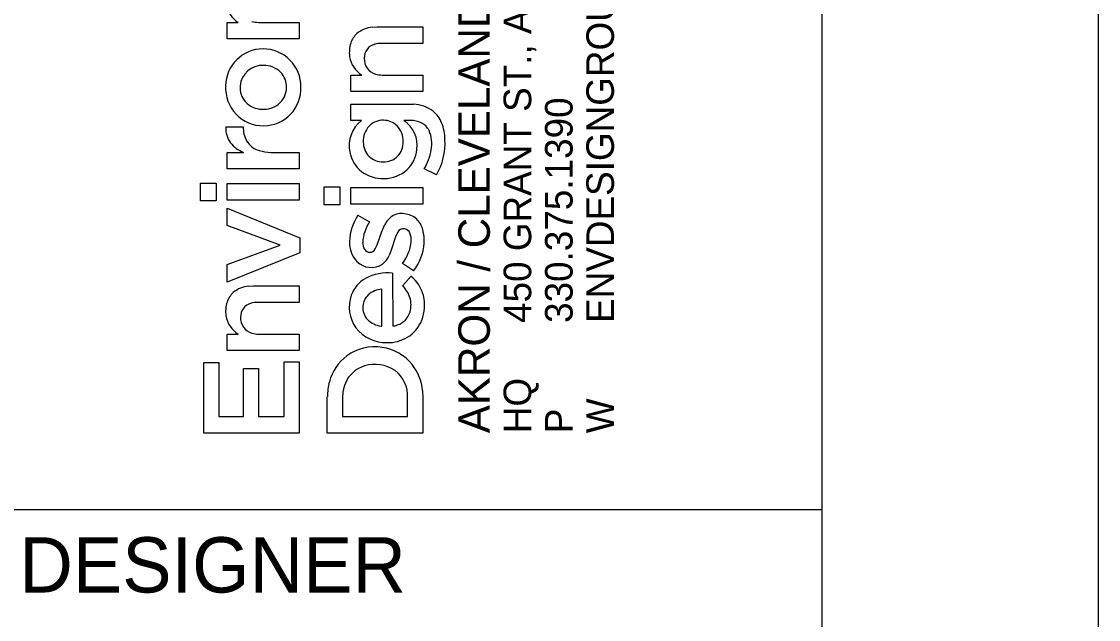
# Model space of a CAD drawing. Extents: x 0 to 34, y 0 to 22.
# Drawn here: x 32.054 to 34, y 2.301 to 3.382 of the extents above; entities that cross this region are included whole.
import ezdxf

# ---------------------------------------------------------------- set-up
doc = ezdxf.new("R2010")
doc.units = 0
for name, color, linetype in [('SH_Border', 7, 'Continuous'), ('SH_Cut_Line', 7, 'Continuous'), ('SH_Data', 7, 'Continuous'), ('SH_Text', 7, 'Continuous')]:
    doc.layers.add(name, color=color, linetype=linetype)

msp = doc.modelspace()

# ---------------------------------------------------------------- linework, layer by layer
at = {"layer": 'SH_Border'}
msp.add_line((32, 2.5), (33.5, 2.5), dxfattribs=at)
msp.add_lwpolyline([(1.5, 21.5), (33.5, 21.5), (33.5, 0.5), (1.5, 0.5)], close=True, dxfattribs=at)
at = {"layer": 'SH_Cut_Line'}
msp.add_lwpolyline([(0, 0), (34, 0), (34, 22), (0, 22)], close=True, dxfattribs=at)
at = {"layer": 'SH_Text'}
for p, q in [((32.4254, 3.3509), (32.4254, 3.3807)), ((32.4254, 3.3807), (32.4455, 3.3807)), ((32.4822, 3.3807), (32.5557, 3.3807)), ((32.5557, 3.3807), (32.5557, 3.351)), ((32.6878, 3.3722), (32.6963, 3.3727)), ((32.6963, 3.3727), (32.7792, 3.3727)), ((32.7792, 3.3727), (32.7792, 3.3429)), ((32.5557, 3.351), (32.4254, 3.3509)), ((32.7792, 3.3429), (32.7048, 3.3428)), ((32.6489, 3.2557), (32.6489, 3.2855)), ((32.6489, 3.2855), (32.669, 3.2855)), ((32.7057, 3.2855), (32.7791, 3.2855)), ((32.7791, 3.2855), (32.7792, 3.2558)), ((32.7792, 3.2558), (32.6489, 3.2557)), ((32.6489, 3.2034), (32.6489, 3.2332)), ((32.6489, 3.2332), (32.7524, 3.2332)), ((32.7524, 3.2332), (32.7619, 3.2329)), ((32.423, 3.1919), (32.4545, 3.1919)), ((32.6684, 3.2034), (32.6489, 3.2034)), ((32.7576, 3.2036), (32.7449, 3.2036)), ((32.4254, 3.1159), (32.4254, 3.1458)), ((32.4254, 3.1458), (32.4547, 3.1458)), ((32.5041, 3.1458), (32.5557, 3.1457)), ((32.5557, 3.1457), (32.5556, 3.1159)), ((32.5556, 3.1159), (32.4254, 3.1159)), ((32.8036, 3.1049), (32.7812, 3.116)), ((32.3771, 3.0582), (32.3771, 3.0903)), ((32.3771, 3.0903), (32.4054, 3.0903)), ((32.4054, 3.0903), (32.4054, 3.0582)), ((32.4254, 3.0594), (32.4254, 3.0893)), ((32.4254, 3.0893), (32.5557, 3.0893)), ((32.5557, 3.0893), (32.5557, 3.0594)), ((32.6005, 3.0511), (32.6005, 3.0832)), ((32.6005, 3.0832), (32.6289, 3.0832)), ((32.6289, 3.0832), (32.6289, 3.0511)), ((32.6489, 3.0523), (32.6489, 3.0822)), ((32.6489, 3.0822), (32.7792, 3.0822)), ((32.7792, 3.0822), (32.7792, 3.0523)), ((32.4054, 3.0582), (32.3771, 3.0582)), ((32.5557, 3.0594), (32.4254, 3.0594)), ((32.4254, 3.0133), (32.4254, 3.0446)), ((32.4254, 3.0446), (32.5567, 2.9913)), ((32.6289, 3.0511), (32.6005, 3.0511)), ((32.7792, 3.0523), (32.6489, 3.0523)), ((32.6615, 3.0321), (32.6827, 3.0203)), ((32.5212, 2.978), (32.4254, 3.0133)), ((32.6967, 2.9787), (32.7048, 3.0026)), ((32.7048, 3.0026), (32.7104, 3.0153)), ((32.7334, 3.001), (32.7298, 2.9933)), ((32.4254, 2.9429), (32.5212, 2.978)), ((32.5567, 2.9913), (32.5567, 2.9644)), ((32.693, 2.9712), (32.6967, 2.9787)), ((32.7298, 2.9933), (32.7221, 2.9688)), ((32.5567, 2.9644), (32.4254, 2.9109)), ((32.7221, 2.9688), (32.7182, 2.9592)), ((32.4254, 2.9109), (32.4254, 2.9429)), ((32.7621, 2.9314), (32.742, 2.9447)), ((32.7245, 2.9275), (32.7246, 2.8319)), ((32.7423, 2.9046), (32.7577, 2.922)), ((32.4644, 2.904), (32.4729, 2.9044)), ((32.4729, 2.9044), (32.5557, 2.9044)), ((32.5557, 2.9044), (32.5557, 2.8746)), ((32.7049, 2.8318), (32.7049, 2.8983)), ((32.5557, 2.8746), (32.4814, 2.8746)), ((32.7036, 2.8317), (32.7049, 2.8318)), ((32.4254, 2.7875), (32.4254, 2.8173)), ((32.4254, 2.8173), (32.4455, 2.8173)), ((32.4822, 2.8173), (32.5557, 2.8173)), ((32.5557, 2.8173), (32.5557, 2.7876)), ((32.5557, 2.7876), (32.4254, 2.7875)), ((32.383, 2.6379), (32.383, 2.766)), ((32.383, 2.766), (32.4101, 2.766)), ((32.4101, 2.766), (32.4101, 2.6683)), ((32.5286, 2.6683), (32.5286, 2.7672)), ((32.5286, 2.7672), (32.5557, 2.7672)), ((32.5557, 2.7672), (32.5557, 2.6379)), ((32.455, 2.6683), (32.455, 2.7549)), ((32.455, 2.7549), (32.4822, 2.7549)), ((32.4822, 2.7549), (32.4822, 2.6683)), ((32.6347, 2.7118), (32.6341, 2.7023)), ((32.7785, 2.715), (32.7792, 2.7021)), ((32.6064, 2.638), (32.6064, 2.704)), ((32.6341, 2.7023), (32.6341, 2.6684)), ((32.7515, 2.6683), (32.7515, 2.7024)), ((32.7792, 2.7021), (32.7792, 2.638)), ((32.4101, 2.6683), (32.455, 2.6683)), ((32.4822, 2.6683), (32.5286, 2.6683)), ((32.6341, 2.6684), (32.7515, 2.6683)), ((32.5557, 2.6379), (32.383, 2.6379)), ((32.7792, 2.638), (32.6064, 2.638))]:
    msp.add_line(p, q, dxfattribs=at)
for points in [[(32.4254, 3.3509), (32.4254, 3.3807), (32.4455, 3.3807)], [(32.4822, 3.3807), (32.5557, 3.3807), (32.5557, 3.351), (32.4254, 3.3509)], [(32.6878, 3.3722), (32.6963, 3.3727), (32.7792, 3.3727), (32.7792, 3.3429), (32.7048, 3.3428)], [(32.6489, 3.2557), (32.6489, 3.2855), (32.669, 3.2855)], [(32.7057, 3.2855), (32.7791, 3.2855), (32.7792, 3.2558), (32.6489, 3.2557)], [(32.6684, 3.2034), (32.6489, 3.2034), (32.6489, 3.2332), (32.7524, 3.2332), (32.7619, 3.2329)], [(32.423, 3.1919), (32.4545, 3.1919)], [(32.7576, 3.2036), (32.7449, 3.2036)], [(32.4254, 3.1159), (32.4254, 3.1458), (32.4547, 3.1458)], [(32.5041, 3.1458), (32.5557, 3.1457), (32.5556, 3.1159), (32.4254, 3.1159)], [(32.8036, 3.1049), (32.7812, 3.116)], [(32.6615, 3.0321), (32.6827, 3.0203)], [(32.693, 2.9712), (32.6967, 2.9787), (32.7048, 3.0026), (32.7104, 3.0153)], [(32.7334, 3.001), (32.7298, 2.9933), (32.7221, 2.9688), (32.7182, 2.9592)], [(32.7621, 2.9314), (32.742, 2.9447)], [(32.7245, 2.9275), (32.7246, 2.8319)], [(32.7423, 2.9046), (32.7577, 2.922)], [(32.4644, 2.904), (32.4729, 2.9044), (32.5557, 2.9044), (32.5557, 2.8746), (32.4814, 2.8746)], [(32.7036, 2.8317), (32.7049, 2.8318), (32.7049, 2.8983)], [(32.4254, 2.7875), (32.4254, 2.8173), (32.4455, 2.8173)], [(32.4822, 2.8173), (32.5557, 2.8173), (32.5557, 2.7876), (32.4254, 2.7875)], [(32.7785, 2.715), (32.7792, 2.7021), (32.7792, 2.638), (32.6064, 2.638)], [(32.6347, 2.7118), (32.6341, 2.7023), (32.6341, 2.6684), (32.7515, 2.6683), (32.7515, 2.7024)], [(32.6064, 2.638), (32.6064, 2.704)]]:
    msp.add_lwpolyline(points, dxfattribs=at)
for points in [[(32.3771, 3.0582), (32.3771, 3.0903), (32.4054, 3.0903), (32.4054, 3.0582)], [(32.4254, 3.0594), (32.4254, 3.0893), (32.5557, 3.0893), (32.5557, 3.0594)], [(32.6005, 3.0511), (32.6005, 3.0832), (32.6289, 3.0832), (32.6289, 3.0511)], [(32.6489, 3.0523), (32.6489, 3.0822), (32.7792, 3.0822), (32.7792, 3.0523)], [(32.4254, 2.9109), (32.4254, 2.9429), (32.5212, 2.978), (32.4254, 3.0133), (32.4254, 3.0446), (32.5567, 2.9913), (32.5567, 2.9644)], [(32.383, 2.6379), (32.383, 2.766), (32.4101, 2.766), (32.4101, 2.6683), (32.455, 2.6683), (32.455, 2.7549), (32.4822, 2.7549), (32.4822, 2.6683), (32.5286, 2.6683), (32.5286, 2.7672), (32.5557, 2.7672), (32.5557, 2.6379)]]:
    msp.add_lwpolyline(points, close=True, dxfattribs=at)
for centre, radius, start, end in [((32.4703, 3.4214), 0.0476, 188.9646, 238.6987), ((32.4703, 3.4214), 0.0476, 188.9646, 238.6987), ((32.4818, 3.4229), 0.0421, 254.0891, 270.5284), ((32.4818, 3.4229), 0.0421, 254.0891, 270.5284), ((32.6922, 3.3225), 0.0499, 94.9706, 130.2248), ((32.6922, 3.3225), 0.0499, 94.9706, 130.2248), ((32.6869, 3.3309), 0.0402, 132.2238, 161.6823), ((32.6869, 3.3309), 0.0402, 132.2238, 161.6823), ((32.4901, 3.2654), 0.0674, 89.8476, 179.6405), ((32.4901, 3.2654), 0.0674, 89.8476, 179.6405), ((32.4906, 3.2647), 0.0681, 359.5401, 90.2114), ((32.4906, 3.2647), 0.0681, 359.5401, 90.2114), ((32.7022, 3.3264), 0.056, 162.274, 187.7917), ((32.7022, 3.3264), 0.056, 162.274, 187.7917), ((32.6983, 3.3169), 0.025, 103.6868, 182.214), ((32.6983, 3.3169), 0.025, 103.6868, 182.214), ((32.7045, 3.2968), 0.046, 89.6051, 105.3303), ((32.7045, 3.2968), 0.046, 89.6051, 105.3303), ((32.6937, 3.3262), 0.0476, 188.9646, 238.6987), ((32.6937, 3.3262), 0.0476, 188.9646, 238.6987), ((32.7008, 3.3138), 0.0276, 175.5844, 255.1382), ((32.7008, 3.3138), 0.0276, 175.5844, 255.1382), ((32.4892, 3.2626), 0.0404, 87.0481, 175.5726), ((32.4892, 3.2626), 0.0404, 87.0481, 175.5726), ((32.492, 3.26), 0.043, 45.8426, 90.9801), ((32.492, 3.26), 0.043, 45.8426, 90.9801), ((32.4946, 3.2642), 0.0382, 357.8857, 44.159), ((32.4946, 3.2642), 0.0382, 357.8857, 44.159), ((32.7053, 3.3277), 0.0421, 254.0891, 270.5284), ((32.7053, 3.3277), 0.0421, 254.0891, 270.5284), ((32.4908, 3.2621), 0.0682, 176.8344, 270.4038), ((32.4908, 3.2621), 0.0682, 176.8344, 270.4038), ((32.4873, 3.2625), 0.0385, 175.1538, 221.1471), ((32.4873, 3.2625), 0.0385, 175.1538, 221.1471), ((32.4912, 3.2614), 0.0675, 270.0624, 2.3776), ((32.4912, 3.2614), 0.0675, 270.0624, 2.3776), ((32.4945, 3.2632), 0.0383, 308.2894, 359.4347), ((32.4945, 3.2632), 0.0383, 308.2894, 359.4347), ((32.4892, 3.2661), 0.0423, 223.0999, 268.8089), ((32.4892, 3.2661), 0.0423, 223.0999, 268.8089), ((32.491, 3.2679), 0.0442, 266.5651, 308.0608), ((32.491, 3.2679), 0.0442, 266.5651, 308.0608), ((32.7591, 3.1679), 0.065, 53.4034, 87.4906), ((32.7591, 3.1679), 0.065, 53.4034, 87.4906), ((32.7652, 3.1804), 0.0514, 21.6075, 50.5577), ((32.7652, 3.1804), 0.0514, 21.6075, 50.5577), ((32.4662, 3.1888), 0.0433, 175.8731, 216.3475), ((32.4662, 3.1888), 0.0433, 175.8731, 216.3475), ((32.5009, 3.1895), 0.0464, 176.9688, 209.6064), ((32.5009, 3.1895), 0.0464, 176.9688, 209.6064), ((32.7029, 3.1581), 0.0569, 127.3748, 192.2247), ((32.7029, 3.1581), 0.0569, 127.3748, 192.2247), ((32.7114, 3.166), 0.0401, 137.4674, 182.3324), ((32.7114, 3.166), 0.0401, 137.4674, 182.3324), ((32.7069, 3.1693), 0.0346, 88.473, 136.4256), ((32.7069, 3.1693), 0.0346, 88.473, 136.4256), ((32.7081, 3.1696), 0.0342, 44.2719, 90.4762), ((32.7081, 3.1696), 0.0342, 44.2719, 90.4762), ((32.7037, 3.166), 0.04, 358.5714, 43.5376), ((32.7037, 3.166), 0.04, 358.5714, 43.5376), ((32.7142, 3.1583), 0.0547, 352.1125, 55.923), ((32.7142, 3.1583), 0.0547, 352.1125, 55.923), ((32.7567, 3.1572), 0.0463, 65.0169, 88.8011), ((32.7567, 3.1572), 0.0463, 65.0169, 88.8011), ((32.7626, 3.1716), 0.0309, 26.2681, 63.803), ((32.7626, 3.1716), 0.0309, 26.2681, 63.803), ((32.7307, 3.1671), 0.0884, 1.1514, 21.3627), ((32.7307, 3.1671), 0.0884, 1.1514, 21.3627), ((32.7357, 3.1615), 0.0595, 349.3073, 23.4307), ((32.7357, 3.1615), 0.0595, 349.3073, 23.4307), ((32.4747, 3.1972), 0.0551, 218.0981, 248.7907), ((32.4747, 3.1972), 0.0551, 218.0981, 248.7907), ((32.4951, 3.1881), 0.0408, 211.9447, 253.2028), ((32.4951, 3.1881), 0.0408, 211.9447, 253.2028), ((32.7065, 3.1637), 0.0351, 178.8821, 271.0837), ((32.7065, 3.1637), 0.0351, 178.8821, 271.0837), ((32.7082, 3.164), 0.0355, 268.2788, 1.5502), ((32.7082, 3.164), 0.0355, 268.2788, 1.5502), ((32.7054, 3.1624), 0.1138, 329.6388, 3.26), ((32.7054, 3.1624), 0.1138, 329.6388, 3.26), ((32.5047, 3.2165), 0.0707, 252.4655, 269.573), ((32.5047, 3.2165), 0.0707, 252.4655, 269.573), ((32.7046, 3.157), 0.0584, 190.7518, 231.2892), ((32.7046, 3.157), 0.0584, 190.7518, 231.2892), ((32.7099, 3.1571), 0.0589, 313.742, 353.8554), ((32.7099, 3.1571), 0.0589, 313.742, 353.8554), ((32.7074, 3.1633), 0.0877, 327.3149, 351.5748), ((32.7074, 3.1633), 0.0877, 327.3149, 351.5748), ((32.7095, 3.159), 0.0605, 269.6361, 312.7088), ((32.7095, 3.159), 0.0605, 269.6361, 312.7088), ((32.7063, 3.1611), 0.0627, 232.4606, 272.5902), ((32.7063, 3.1611), 0.0627, 232.4606, 272.5902), ((32.7364, 2.9826), 0.0897, 146.531, 178.7571), ((32.7364, 2.9826), 0.0897, 146.531, 178.7571), ((32.7452, 2.9789), 0.0749, 146.5112, 176.9101), ((32.7452, 2.9789), 0.0749, 146.5112, 176.9101), ((32.7466, 2.9971), 0.0405, 125.5118, 153.4159), ((32.7466, 2.9971), 0.0405, 125.5118, 153.4159), ((32.7406, 3.0026), 0.0326, 80.1719, 122.5197), ((32.7406, 3.0026), 0.0326, 80.1719, 122.5197), ((32.7428, 2.9982), 0.0367, 47.7934, 84.6892), ((32.7428, 2.9982), 0.0367, 47.7934, 84.6892), ((32.7379, 2.9946), 0.0427, 14.9966, 46.2063), ((32.7379, 2.9946), 0.0427, 14.9966, 46.2063), ((32.7438, 2.9963), 0.0114, 76.6609, 155.7053), ((32.7438, 2.9963), 0.0114, 76.6609, 155.7053), ((32.744, 2.9951), 0.0126, 21.5098, 78.5262), ((32.744, 2.9951), 0.0126, 21.5098, 78.5262), ((32.7259, 2.9877), 0.0321, 354.5726, 22.068), ((32.7259, 2.9877), 0.0321, 354.5726, 22.068), ((32.7104, 2.9867), 0.0712, 355.8306, 15.3914), ((32.7104, 2.9867), 0.0712, 355.8306, 15.3914), ((32.6967, 2.9824), 0.0501, 177.5366, 222.7932), ((32.6967, 2.9824), 0.0501, 177.5366, 222.7932), ((32.6931, 2.9823), 0.0228, 178.4747, 211.0868), ((32.6931, 2.9823), 0.0228, 178.4747, 211.0868), ((32.6825, 2.9915), 0.0757, 321.811, 354.7969), ((32.6825, 2.9915), 0.0757, 321.811, 354.7969), ((32.6895, 2.9882), 0.0922, 321.9777, 355.8738), ((32.6895, 2.9882), 0.0922, 321.9777, 355.8738), ((32.6833, 2.9767), 0.0115, 212.2368, 268.3777), ((32.6833, 2.9767), 0.0115, 212.2368, 268.3777), ((32.6834, 2.9759), 0.0107, 267.716, 333.7337), ((32.6834, 2.9759), 0.0107, 267.716, 333.7337), ((32.681, 2.9758), 0.0408, 308.0877, 335.9874), ((32.681, 2.9758), 0.0408, 308.0877, 335.9874), ((32.686, 2.9753), 0.0375, 225.9854, 302.4797), ((32.686, 2.9753), 0.0375, 225.9854, 302.4797), ((32.7152, 2.8441), 0.0838, 83.615, 118.2876), ((32.7152, 2.8441), 0.0838, 83.615, 118.2876), ((32.7174, 2.8717), 0.0644, 13.5336, 51.3615), ((32.7174, 2.8717), 0.0644, 13.5336, 51.3615), ((32.4687, 2.8543), 0.0499, 94.9696, 130.2225), ((32.4687, 2.8543), 0.0499, 94.9696, 130.2225), ((32.7024, 2.8691), 0.0558, 118.8308, 160.6244), ((32.7024, 2.8691), 0.0558, 118.8308, 160.6244), ((32.7038, 2.8656), 0.0549, 19.0357, 45.4406), ((32.7038, 2.8656), 0.0549, 19.0357, 45.4406), ((32.4635, 2.8626), 0.0402, 132.2219, 161.6818), ((32.4635, 2.8626), 0.0402, 132.2219, 161.6818), ((32.7104, 2.8661), 0.0644, 160.5201, 215.7831), ((32.7104, 2.8661), 0.0644, 160.5201, 215.7831), ((32.7005, 2.8663), 0.0298, 132.9851, 177.179), ((32.7005, 2.8663), 0.0298, 132.9851, 177.179), ((32.7079, 2.8561), 0.0424, 94.008, 130.8817), ((32.7079, 2.8561), 0.0424, 94.008, 130.8817), ((32.7107, 2.8697), 0.047, 344.6059, 17.007), ((32.7107, 2.8697), 0.047, 344.6059, 17.007), ((32.7064, 2.8692), 0.0758, 339.3542, 13.3785), ((32.7064, 2.8692), 0.0758, 339.3542, 13.3785), ((32.4787, 2.8582), 0.056, 162.2736, 187.7919), ((32.4787, 2.8582), 0.056, 162.2736, 187.7919), ((32.4748, 2.8487), 0.025, 103.6865, 182.2187), ((32.4748, 2.8487), 0.025, 103.6865, 182.2187), ((32.4811, 2.8286), 0.046, 89.6049, 105.3284), ((32.4811, 2.8286), 0.046, 89.6049, 105.3284), ((32.7017, 2.865), 0.0311, 175.0013, 223.283), ((32.7017, 2.865), 0.0311, 175.0013, 223.283), ((32.4703, 2.858), 0.0476, 188.962, 238.7037), ((32.4703, 2.858), 0.0476, 188.962, 238.7037), ((32.4773, 2.8456), 0.0276, 175.5854, 255.1439), ((32.4773, 2.8456), 0.0276, 175.5854, 255.1439), ((32.7089, 2.8736), 0.0423, 225.0619, 262.7974), ((32.7089, 2.8736), 0.0423, 225.0619, 262.7974), ((32.7224, 2.8671), 0.035, 288.0077, 343.5508), ((32.7224, 2.8671), 0.035, 288.0077, 343.5508), ((32.7189, 2.8652), 0.0626, 300.9427, 338.7323), ((32.7189, 2.8652), 0.0626, 300.9427, 338.7323), ((32.7125, 2.8705), 0.0687, 217.7452, 271.6543), ((32.7125, 2.8705), 0.0687, 217.7452, 271.6543), ((32.7247, 2.8522), 0.0202, 269.7003, 294.8711), ((32.7247, 2.8522), 0.0202, 269.7003, 294.8711), ((32.4818, 2.8595), 0.0422, 254.0916, 270.5284), ((32.4818, 2.8595), 0.0422, 254.0916, 270.5284), ((32.7155, 2.8724), 0.0706, 269.2048, 300.3341), ((32.7155, 2.8724), 0.0706, 269.2048, 300.3341), ((32.6923, 2.7079), 0.0864, 81.194, 125.9984), ((32.6923, 2.7079), 0.0864, 81.194, 125.9984), ((32.6946, 2.7113), 0.0827, 37.8521, 82.402), ((32.6946, 2.7113), 0.0827, 37.8521, 82.402), ((32.6939, 2.7089), 0.0865, 127.2362, 165.148), ((32.6939, 2.7089), 0.0865, 127.2362, 165.148), ((32.6889, 2.7078), 0.054, 106.1881, 157.3861), ((32.6889, 2.7078), 0.054, 106.1881, 157.3861), ((32.6928, 2.6986), 0.0639, 55.6727, 107.2093), ((32.6928, 2.6986), 0.0639, 55.6727, 107.2093), ((32.6929, 2.705), 0.0587, 357.4662, 52.2665), ((32.6929, 2.705), 0.0587, 357.4662, 52.2665), ((32.6859, 2.7057), 0.0931, 5.7333, 37.304), ((32.6859, 2.7057), 0.0931, 5.7333, 37.304), ((32.7143, 2.7028), 0.1078, 164.7861, 179.3704), ((32.7143, 2.7028), 0.1078, 164.7861, 179.3704), ((32.6983, 2.7039), 0.0641, 157.3571, 172.9275), ((32.6983, 2.7039), 0.0641, 157.3571, 172.9275)]:
    msp.add_arc(centre, radius, start, end, dxfattribs=at)

# ---------------------------------------------------------------- texts
at = {"layer": 'SH_Data'}
msp.add_text('DESIGNER', height=0.1, dxfattribs=at).set_placement((32.05, 2.35))
at = {"layer": 'SH_Text'}
for s, height, p in [('450 GRANT ST., AKRON, OH  44311', 0.049846, (32.9749, 2.8374)), ('AKRON / CLEVELAND / COLUMBUS', 0.056969, (32.9001, 2.638)), ('ENVDESIGNGROUP.COM', 0.049846, (33.1244, 2.8374)), ('330.375.1390', 0.049846, (33.0497, 2.8374)), ('HQ ', 0.04985, (32.9749, 2.638)), ('W', 0.0498, (33.1244, 2.638)), ('P', 0.0498, (33.0497, 2.638))]:
    msp.add_text(s, height=height, rotation=90, dxfattribs=at).set_placement(p)

doc.saveas('drawing.dxf')
